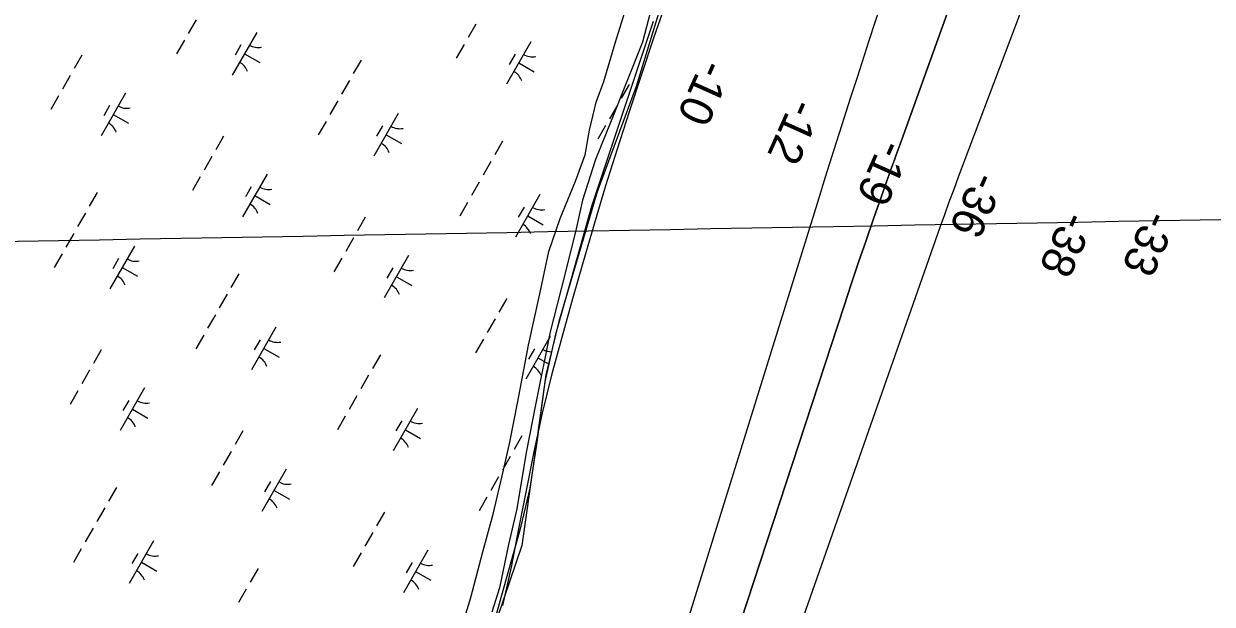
# Model space of a CAD drawing. Extents: x 3930721 to 3950824, y 220441 to 242861.
# Drawn here: x 3941236 to 3942447, y 235919 to 236510 of the extents above; entities that cross this region are included whole.
import ezdxf

# ---------------------------------------------------------------- set-up
doc = ezdxf.new("R2010")
doc.units = 0
for name, color, linetype in [('V-GRID-MAJR', 7, 'Continuous'), ('V-RIVR-EDGE', 7, 'Continuous'), ('V-RIVR-JETY', 7, 'Continuous'), ('V-RIVR-RANG', 7, 'Continuous'), ('V-RRAP-FSHR', 7, 'Continuous'), ('V-TOPO-DPTH', 7, 'Continuous'), ('V-TOPO-MINR', 7, 'Continuous'), ('V-WETL-SWMP', 7, 'Continuous')]:
    doc.layers.add(name, color=color, linetype=linetype)

msp = doc.modelspace()

# ---------------------------------------------------------------- linework, layer by layer
at = {"layer": 'V-GRID-MAJR'}
msp.add_spline([(3939227.7, 236252.5), (3940647.6, 236278.1), (3945968.1, 236374.4), (3948134.1, 236413.9)], degree=3, dxfattribs=at)
at = {"layer": 'V-RIVR-EDGE'}
msp.add_lwpolyline([(3942388.1, 237996.2), (3942359.5, 237893.9), (3942342.1, 237826.3), (3942313.4, 237743.4), (3942293.9, 237654.3), (3942254, 237535.6), (3942177.2, 237310.3), (3942136.3, 237209), (3942081, 237057.5), (3942021.6, 236902.9), (3941957.1, 236759.6), (3941930.5, 236693), (3941910.1, 236611.1), (3941859.9, 236446.3), (3941820, 236338.8), (3941781.1, 236206.8), (3941767.8, 236152.5), (3941755.5, 236064.5), (3941743.2, 235978.5), (3941712.5, 235887.4)], dxfattribs=at)
at = {"layer": 'V-RIVR-JETY'}
for points in [[(3941676.9, 235877.7), (3941691.2, 235925.6), (3941703.5, 235971.9), (3941714.2, 236010.5), (3941724.6, 236055.3), (3941731.2, 236083.7), (3941739.2, 236125.1), (3941750.1, 236182.8), (3941761.7, 236235), (3941770.9, 236278.2), (3941782.3, 236311.7), (3941798, 236349.8), (3941807.8, 236376.6), (3941812.4, 236401.6), (3941819, 236430.4), (3941827.1, 236451.4), (3941838.6, 236490.3), (3941849.6, 236526.5), (3941857.5, 236557.7), (3941869, 236600.6), (3941881.6, 236638.3)], [(3941878.3, 236537.1), (3941866.4, 236491.5), (3941834.4, 236411.1), (3941818.3, 236371.8), (3941805.2, 236330.5), (3941798.1, 236298.2), (3941783.3, 236240.2), (3941772.2, 236196.1), (3941757.5, 236123.6), (3941747.9, 236073.4), (3941738.1, 236016), (3941729.8, 235979.4), (3941720.6, 235935.4), (3941712.9, 235910.5)]]:
    msp.add_lwpolyline(points, dxfattribs=at)
at = {"layer": 'V-RRAP-FSHR'}
msp.add_lwpolyline([(3941891, 236534.2), (3941877.9, 236496.4), (3941865.5, 236458.5), (3941852.7, 236420.5), (3941840.5, 236382.4), (3941828.8, 236344.9), (3941817.1, 236305.8), (3941805.7, 236267.5), (3941794.9, 236229.7), (3941784.1, 236190.5), (3941773.5, 236151.9), (3941764.1, 236113.4), (3941755.6, 236073.9), (3941747.7, 236034.7), (3941740, 235995.5), (3941732.5, 235956.3), (3941723.6, 235917.2)], dxfattribs=at)
at = {"layer": 'V-TOPO-DPTH'}
for points in [[(3942475.6, 237118.1), (3942443, 237029.4), (3942410.1, 236940.9), (3942341.2, 236756.8), (3942332.7, 236734.3), (3942324.1, 236711.8), (3942315.5, 236689.3), (3942306.8, 236666.9), (3942298.1, 236644.4), (3942289.5, 236622), (3942280.9, 236599.5), (3942272.4, 236576.9), (3942188.3, 236353.9), (3942183.6, 236341.1), (3942178.8, 236328.2), (3942174.2, 236315.3), (3942169.6, 236302.4), (3941781.7, 235197.5)], [(3942475.6, 237118.1), (3942443, 237029.4), (3942410.1, 236940.9), (3942341.2, 236756.8), (3942332.7, 236734.3), (3942324.1, 236711.8), (3942315.5, 236689.3), (3942306.8, 236666.9), (3942298.1, 236644.4), (3942289.5, 236622), (3942280.9, 236599.5), (3942272.4, 236576.9), (3942188.3, 236353.9), (3942183.6, 236341.1), (3942178.8, 236328.2), (3942174.2, 236315.3), (3942169.6, 236302.4), (3941781.7, 235197.5)], [(3941742.9, 235219.4), (3942071.9, 236222.7), (3942079.2, 236244.9), (3942086.7, 236267.1), (3942094.3, 236289.2), (3942102, 236311.3), (3942113.7, 236344.9), (3942115.6, 236350.2), (3942117.5, 236355.5), (3942119.3, 236360.8), (3942121.2, 236366.1), (3942123.1, 236371.4), (3942125, 236376.7), (3942127, 236382), (3942128.9, 236387.3), (3942252.6, 236731.7)]]:
    msp.add_lwpolyline(points, dxfattribs=at)
at = {"layer": 'V-TOPO-MINR'}
for points in [[(3942411.8, 237345.4), (3942268.2, 236987), (3942254.2, 236951.6), (3942240.5, 236916.1), (3942227.1, 236880.5), (3942214, 236844.8), (3942212.1, 236839.7), (3942200.3, 236806.4), (3942188.6, 236773.1), (3942177.3, 236739.6), (3942166.2, 236706), (3942133.4, 236604.8), (3942121.3, 236567.4), (3942109.2, 236530.1), (3942097.1, 236492.7), (3942085.1, 236455.3), (3942078.2, 236434.1), (3942069.6, 236407.3), (3942061.1, 236380.5), (3942052.7, 236353.7), (3942044.3, 236326.9), (3941811.1, 235576.1)], [(3942475.6, 237118.1), (3942443, 237029.4), (3942410.1, 236940.9), (3942341.2, 236756.8), (3942332.7, 236734.3), (3942324.1, 236711.8), (3942315.5, 236689.3), (3942306.8, 236666.9), (3942298.1, 236644.4), (3942289.5, 236622), (3942280.9, 236599.5), (3942272.4, 236576.9), (3942188.3, 236353.9), (3942183.6, 236341.1), (3942178.8, 236328.2), (3942174.2, 236315.3), (3942169.6, 236302.4), (3941781.7, 235197.5)], [(3942252.6, 236731.7), (3942128.9, 236387.3), (3942127, 236382), (3942125, 236376.7), (3942123.1, 236371.4), (3942121.2, 236366.1), (3942119.3, 236360.8), (3942117.5, 236355.5), (3942115.6, 236350.2), (3942113.7, 236344.9), (3942102, 236311.3), (3942094.3, 236289.2), (3942086.7, 236267.1), (3942079.2, 236244.9), (3942071.9, 236222.7), (3941742.9, 235219.4)]]:
    msp.add_lwpolyline(points, dxfattribs=at)
at = {"layer": 'V-WETL-SWMP'}
for p, q in [((3941411.3, 236514.2), (3941403.3, 236500.3)), ((3941696.4, 236509.9), (3941688.5, 236496)), ((3941814.6, 236324.4), (3941877.4, 236512.9)), ((3941473.1, 236501.3), (3941448.2, 236457.9)), ((3941399.3, 236493.4), (3941391.4, 236479.5)), ((3941456.9, 236488.7), (3941451, 236478.3)), ((3941684.5, 236489.1), (3941676.5, 236475.2)), ((3941752.6, 236491.9), (3941727.8, 236448.5)), ((3941294.9, 236478.3), (3941287, 236464.4)), ((3941460.7, 236479.6), (3941476.3, 236470.7)), ((3941579.5, 236473.2), (3941571.5, 236459.3)), ((3941736.5, 236479.2), (3941730.5, 236468.8)), ((3941740.2, 236470.2), (3941755.8, 236461.2)), ((3941283, 236457.5), (3941275.1, 236443.6)), ((3941567.5, 236452.3), (3941559.6, 236438.5)), ((3941339.2, 236439.4), (3941314.4, 236396.1)), ((3941852.7, 236448.1), (3941844.7, 236434.2)), ((3941271.1, 236436.6), (3941263.1, 236422.7)), ((3941323.1, 236426.8), (3941317.1, 236416.4)), ((3941555.6, 236431.5), (3941547.6, 236417.6)), ((3941840.8, 236427.2), (3941832.8, 236413.3)), ((3941326.8, 236417.7), (3941342.4, 236408.8)), ((3941617.4, 236418.7), (3941592.6, 236375.3)), ((3941543.7, 236410.7), (3941535.7, 236396.8)), ((3941601.3, 236406), (3941595.3, 236395.6)), ((3941828.8, 236406.4), (3941820.9, 236392.5)), ((3941439.3, 236395.6), (3941431.3, 236381.7)), ((3941605, 236397), (3941620.6, 236388)), ((3941723.8, 236390.5), (3941715.8, 236376.6)), ((3941427.4, 236374.8), (3941419.4, 236360.9)), ((3941711.9, 236369.7), (3941703.9, 236355.8)), ((3941415.4, 236354), (3941407.5, 236340.1)), ((3941483.6, 236356.8), (3941458.7, 236313.4)), ((3941467.4, 236344.1), (3941461.5, 236333.7)), ((3941699.9, 236348.8), (3941692, 236335)), ((3941310.4, 236338.1), (3941302.4, 236324.2)), ((3941471.1, 236335.1), (3941486.8, 236326.1)), ((3941688, 236328), (3941680.1, 236314.1)), ((3941761.8, 236336), (3941736.9, 236292.6)), ((3941298.5, 236317.2), (3941290.5, 236303.4)), ((3941745.6, 236323.3), (3941739.7, 236312.9)), ((3941778.1, 236193.8), (3941814.6, 236324.4)), ((3941583.6, 236312.9), (3941575.7, 236299.1)), ((3941749.3, 236314.3), (3941765, 236305.4)), ((3941286.5, 236296.4), (3941278.6, 236282.5)), ((3941571.7, 236292.1), (3941563.8, 236278.2)), ((3941348.4, 236283.6), (3941323.5, 236240.2)), ((3941274.6, 236275.6), (3941266.7, 236261.7)), ((3941332.2, 236270.9), (3941326.3, 236260.5)), ((3941559.8, 236271.3), (3941551.8, 236257.4)), ((3941627.9, 236274.1), (3941603, 236230.7)), ((3941335.9, 236261.9), (3941351.6, 236252.9)), ((3941454.7, 236255.4), (3941446.8, 236241.5)), ((3941611.8, 236261.5), (3941605.8, 236251)), ((3941615.5, 236252.4), (3941631.1, 236243.5)), ((3941442.8, 236234.6), (3941434.9, 236220.7)), ((3941728, 236230.3), (3941720, 236216.4)), ((3941430.9, 236213.7), (3941422.9, 236199.9)), ((3941716, 236209.5), (3941708.1, 236195.6)), ((3941492.7, 236200.9), (3941467.9, 236157.5)), ((3941419, 236192.9), (3941411, 236179)), ((3941476.6, 236188.2), (3941470.6, 236177.8)), ((3941704.1, 236188.6), (3941696.2, 236174.7)), ((3941772.2, 236191.4), (3941747.4, 236148.1)), ((3941767.2, 236145.1), (3941778.1, 236193.8)), ((3941314.6, 236177.8), (3941306.6, 236164)), ((3941480.3, 236179.2), (3941495.9, 236170.3)), ((3941599.1, 236172.7), (3941591.1, 236158.8)), ((3941756.1, 236178.8), (3941750.1, 236168.4)), ((3941759.8, 236169.7), (3941771.2, 236163.2)), ((3941302.6, 236157), (3941294.7, 236143.1)), ((3941587.1, 236151.9), (3941579.2, 236138)), ((3941290.7, 236136.2), (3941282.8, 236122.3)), ((3941358.8, 236139), (3941334, 236095.6)), ((3941758.9, 236083.8), (3941767.2, 236145.1)), ((3941342.7, 236126.4), (3941336.7, 236115.9)), ((3941575.2, 236131.1), (3941567.3, 236117.2)), ((3941346.4, 236117.3), (3941362, 236108.4)), ((3941563.3, 236110.3), (3941555.3, 236096.4)), ((3941637, 236118.2), (3941612.2, 236074.8)), ((3941620.9, 236105.6), (3941614.9, 236095.2)), ((3941458.9, 236095.2), (3941451, 236081.3)), ((3941624.6, 236096.5), (3941640.2, 236087.6)), ((3941743.4, 236090.1), (3941735.5, 236076.2)), ((3941447, 236074.4), (3941439, 236060.5)), ((3941751.9, 236036.9), (3941758.9, 236083.8)), ((3941731.5, 236069.2), (3941723.5, 236055.4)), ((3941435.1, 236053.5), (3941427.1, 236039.6)), ((3941503.2, 236056.3), (3941478.3, 236013)), ((3941330, 236037.6), (3941322.1, 236023.7)), ((3941487, 236043.7), (3941481.1, 236033.3)), ((3941719.6, 236048.4), (3941711.6, 236034.5)), ((3941742.6, 235998.3), (3941751.9, 236036.9)), ((3941490.8, 236034.6), (3941506.4, 236025.7)), ((3941707.6, 236027.6), (3941699.7, 236013.7)), ((3941318.1, 236016.8), (3941310.1, 236002.9)), ((3941603.3, 236012.5), (3941595.3, 235998.6)), ((3941306.2, 235996), (3941298.2, 235982.1)), ((3941591.3, 235991.7), (3941583.4, 235977.8)), ((3941698.2, 235840), (3941742.6, 235998.3)), ((3941368, 235983.1), (3941343.1, 235939.7)), ((3941294.2, 235975.2), (3941286.3, 235961.3)), ((3941351.8, 235970.5), (3941345.9, 235960.1)), ((3941579.4, 235970.9), (3941571.4, 235957)), ((3941647.5, 235973.7), (3941622.7, 235930.3)), ((3941355.6, 235961.4), (3941371.2, 235952.5)), ((3941474.4, 235955), (3941466.4, 235941.1)), ((3941631.4, 235961), (3941625.4, 235950.6)), ((3941635.1, 235952), (3941650.7, 235943)), ((3941462.4, 235934.1), (3941454.5, 235920.3))]:
    msp.add_line(p, q, dxfattribs=at)
for centre, start, end in [((3941474.6, 236503.5), 239.4279, 280.9715), ((3941754.1, 236494), 239.4279, 280.9715), ((3941447.1, 236455.6), 19.4279, 60.9715), ((3941726.7, 236446.1), 19.4279, 60.9715), ((3941340.7, 236441.6), 239.4279, 280.9715), ((3941313.3, 236393.7), 19.4279, 60.9715), ((3941618.9, 236420.8), 239.4279, 280.9715), ((3941591.5, 236372.9), 19.4279, 60.9715), ((3941485.1, 236358.9), 239.4279, 280.9715), ((3941457.6, 236311), 19.4279, 60.9715), ((3941763.3, 236338.2), 239.4279, 280.9715), ((3941735.8, 236290.2), 19.4279, 60.9715), ((3941349.9, 236285.7), 239.4279, 280.9715), ((3941629.4, 236276.3), 239.4279, 280.9715), ((3941322.4, 236237.8), 19.4279, 60.9715), ((3941602, 236228.3), 19.4279, 60.9715), ((3941494.2, 236203.1), 239.4279, 280.9715), ((3941466.8, 236155.1), 19.4279, 60.9715), ((3941773.7, 236193.6), 239.4279, 271.0947), ((3941746.3, 236145.7), 19.4279, 60.9715), ((3941360.3, 236141.2), 239.4279, 280.9715), ((3941332.9, 236093.2), 19.4279, 60.9715), ((3941638.6, 236120.4), 239.4279, 280.9715), ((3941611.1, 236072.5), 19.4279, 60.9715), ((3941504.7, 236058.5), 239.4279, 280.9715), ((3941477.2, 236010.6), 19.4279, 60.9715), ((3941369.5, 235985.3), 239.4279, 280.9715), ((3941342, 235937.3), 19.4279, 60.9715), ((3941649, 235975.8), 239.4279, 280.9715), ((3941621.6, 235927.9), 19.4279, 60.9715)]:
    msp.add_arc(centre, 17.6, start, end, dxfattribs=at)

# ---------------------------------------------------------------- texts
at = {"layer": 'V-RIVR-RANG'}
for s, rotation, p in [('-10', 245.8983, (3941927.6, 236475.7)), ('-12', 245.8983, (3942019.4, 236435.9)), ('-19', 245.8983, (3942110.2, 236394)), ('-36', 245.8983, (3942205.2, 236361.4)), ('-33', 246.041, (3942380.9, 236322)), ('-38', 245.8983, (3942296.7, 236321.1))]:
    msp.add_text(s, height=33.5, rotation=rotation, dxfattribs=at).set_placement(p)

doc.saveas('drawing.dxf')
